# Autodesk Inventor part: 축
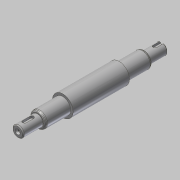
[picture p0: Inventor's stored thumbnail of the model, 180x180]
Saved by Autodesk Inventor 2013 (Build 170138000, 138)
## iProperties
Created: 2019-06
Part Number: 축
Material: 강철, 연강
Document SubType Name: Modeling
Designer: mduedu
Density: 1 g/cm^3
Author: mduedu
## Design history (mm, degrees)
sketch "스케치1"
  geometry: L1 (0, 0)-(21, 0); L2 (21, 0)-(21, 6); L3 (21, 6)-(0, 6); L4 (0, 6)-(0, 0); L5 (21, 0)-(48, 0); L6 (48, 0)-(48, 8.5); L7 (48, 8.5)-(21, 8.5); L8 (21, 8.5)-(21, 0); L9 (48, 0)-(108, 0); L10 (108, 0)-(108, 11); L11 (108, 11)-(48, 11); L12 (48, 11)-(48, 0); L13 (108, 0)-(135, 0); L14 (135, 0)-(135, 8.5); L15 (135, 8.5)-(108, 8.5); L16 (108, 8.5)-(108, 0); L17 (135, 0)-(154, 0); L18 (154, 0)-(154, 6); L19 (154, 6)-(135, 6); L20 (135, 6)-(135, 0)
  constraints: 40 end point, 10 parallel, 5 horizontal, 5 perpendicular
  dimensions: "d3" = 60 distance of L10.end L11.end; "d4" = 17 diameter of L15 L13; "d5" = 22 diameter of L11 L9; "d6" = 17 diameter of L7 L5; "d7" = 12 diameter of L3 L1; "d40" = 19 distance of L18.end L19.end; "d41" = 12 diameter of L19 L17; "d42" = 46 distance between parallel lines of L10 L18; "d43" = 133 distance between parallel lines of L8 L18; "d44" = 154 distance between parallel lines of L4 L18
revolve "회전1" sketch "스케치1" stored, may be unused: angle "d9" = 90 deg
node "작업 평면1"
sketch "스케치2" dims "d10" = 12
  geometry: L1 (3.5, -2)-(-4.5, -2); L2 (-4.5, -2)-(-4.5, 2); L3 (-4.5, 2)-(3.5, 2); L4 (3.5, 2)-(3.5, -2); L5 (-10.5, 8.5)-(-10.5, -8.5) reference; 3 further points
  constraints: 8 end point, 2 midpoint, 2 parallel, 2 vertical alignment, 1 horizontal, 1 horizontal alignment, 1 perpendicular, 4 other
  dimensions: "d12" = 4 dimension on L5; "d13" = 4 distance between parallel lines of L3 L1
extrude "돌출1" cut sketch "스케치2" distance "d14" = 2.5; taper "d15" = 0 deg
sketch "스케치4"
  geometry: L1 (-143.5, 2)-(-135.5, 2); L2 (-135.5, 2)-(-135.5, -2); L3 (-135.5, -2)-(-143.5, -2); L4 (-143.5, -2)-(-143.5, 2); L5 (-143.5, 6)-(-143.5, -6) reference; 2 further points
  constraints: 8 end point, 2 parallel, 1 collinear, 1 horizontal, 1 horizontal alignment, 1 midpoint, 1 perpendicular, 1 vertical alignment, 2 other
  dimensions: "d50" = 10 dimension on L4; "d52" = 4 distance between parallel lines of L1 L3
extrude "돌출2" cut sketch "스케치4" distance "d53" = 2.5; taper "d54" = 0 deg
hole "구멍1" diameter "d18" = 3.242; stored, may be unused: countersink angle "d22" = 90 deg, drill point angle "d24" = 118 deg; dims "d16" = 10, "d17" = 10, "d19" = 8, "d20" = 4, "d21" = 2, "d23" = 10
sketch "스케치3"
  geometry: L1 (0, 0)-(2, 0); L2 (2, 0)-(2, -1.621); L3 (0, -2.776)-(0, 0); L4 (10, -1.621)-(0, -1.621) reference; L5 (0, -2.776)-(2, -1.621)
  constraints: 8 end point, 1 horizontal, 1 parallel, 1 perpendicular, 1 point on line
  dimensions: "d25" = 2 distance between parallel lines of L2 L3; "d27" = 30 deg angle of L1 L5
revolve "회전2" sketch "스케치3" stored, may be unused: angle "d29" = 90 deg
chamfer "모따기1" distance "d30" = 1.82; stored, may be unused: second distance "d31" = 2, angle "d32" = 30 deg
fillet "모깎기1" dims "d36" = 2, "d37" = 1
chamfer "모따기3" distance "d45" = 1.82; stored, may be unused: second distance "d46" = 2, angle "d47" = 30 deg
fillet "모깎기2" dims "d48" = 2, "d49" = 1
chamfer "모따기4" distance "d55" = 1; stored, may be unused: second distance "d56" = 2, angle "d57" = 30 deg
node "솔리드1"
